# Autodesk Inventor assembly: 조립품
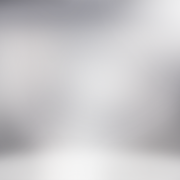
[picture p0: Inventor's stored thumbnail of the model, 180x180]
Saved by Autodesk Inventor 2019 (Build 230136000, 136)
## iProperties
Created: 2020-07
Part Number: 조립품
Material: 일반
Document SubType Name: Assembly
Designer: Admin
Author: Admin
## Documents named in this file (1)
- C:\Users\Admin\Desktop\700707V1016\조립품.iam
